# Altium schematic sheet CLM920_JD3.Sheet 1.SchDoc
size 431 x 279 mm
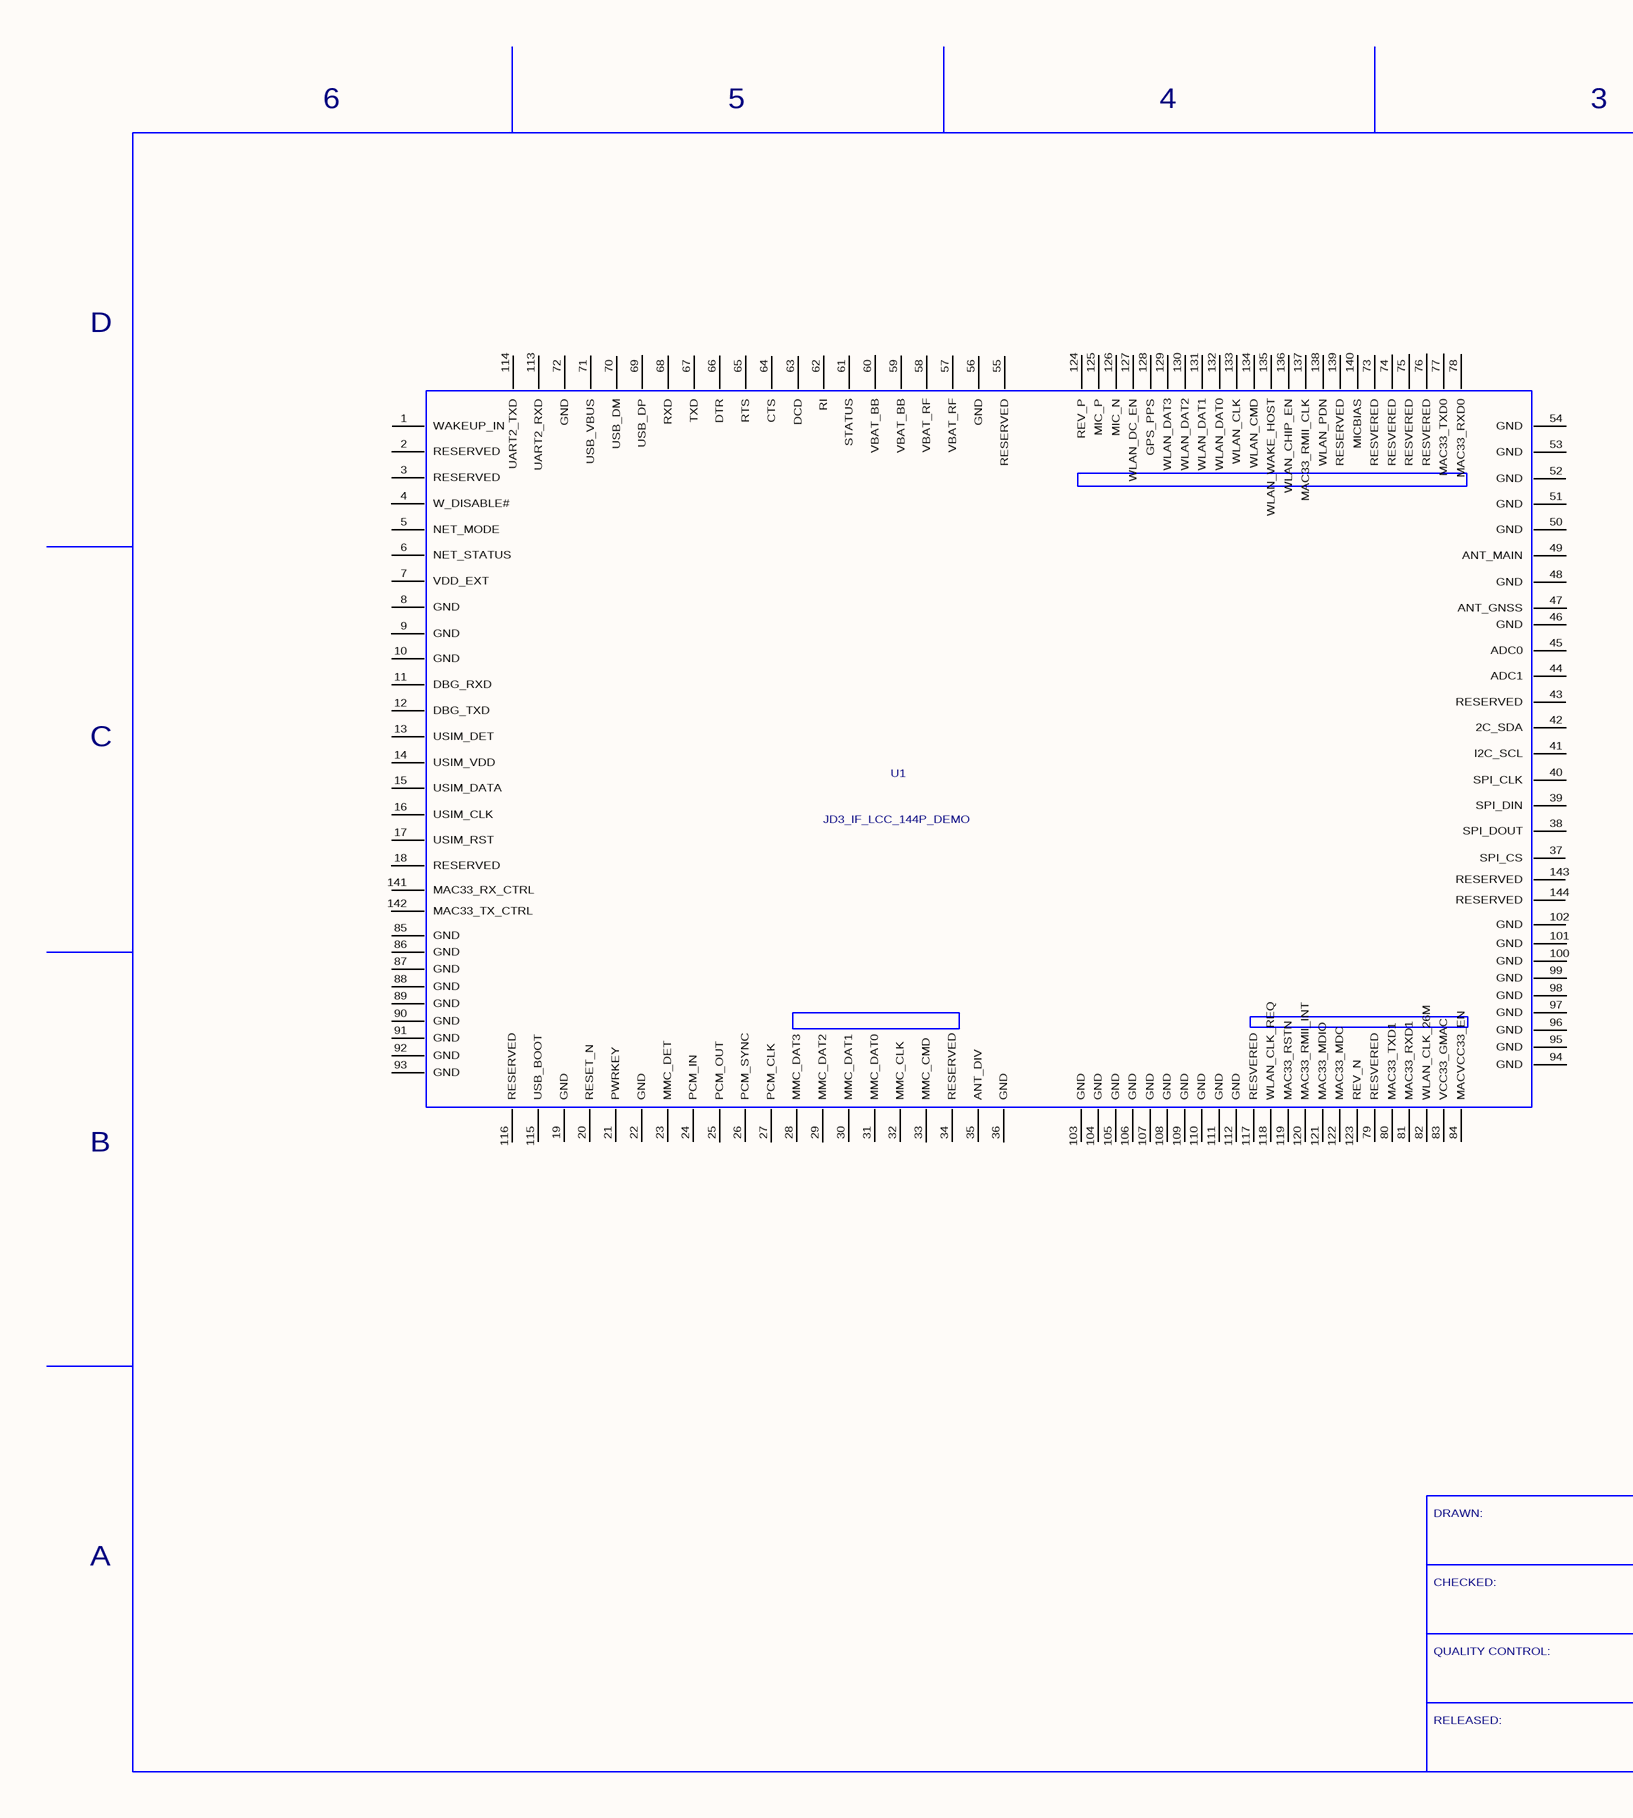
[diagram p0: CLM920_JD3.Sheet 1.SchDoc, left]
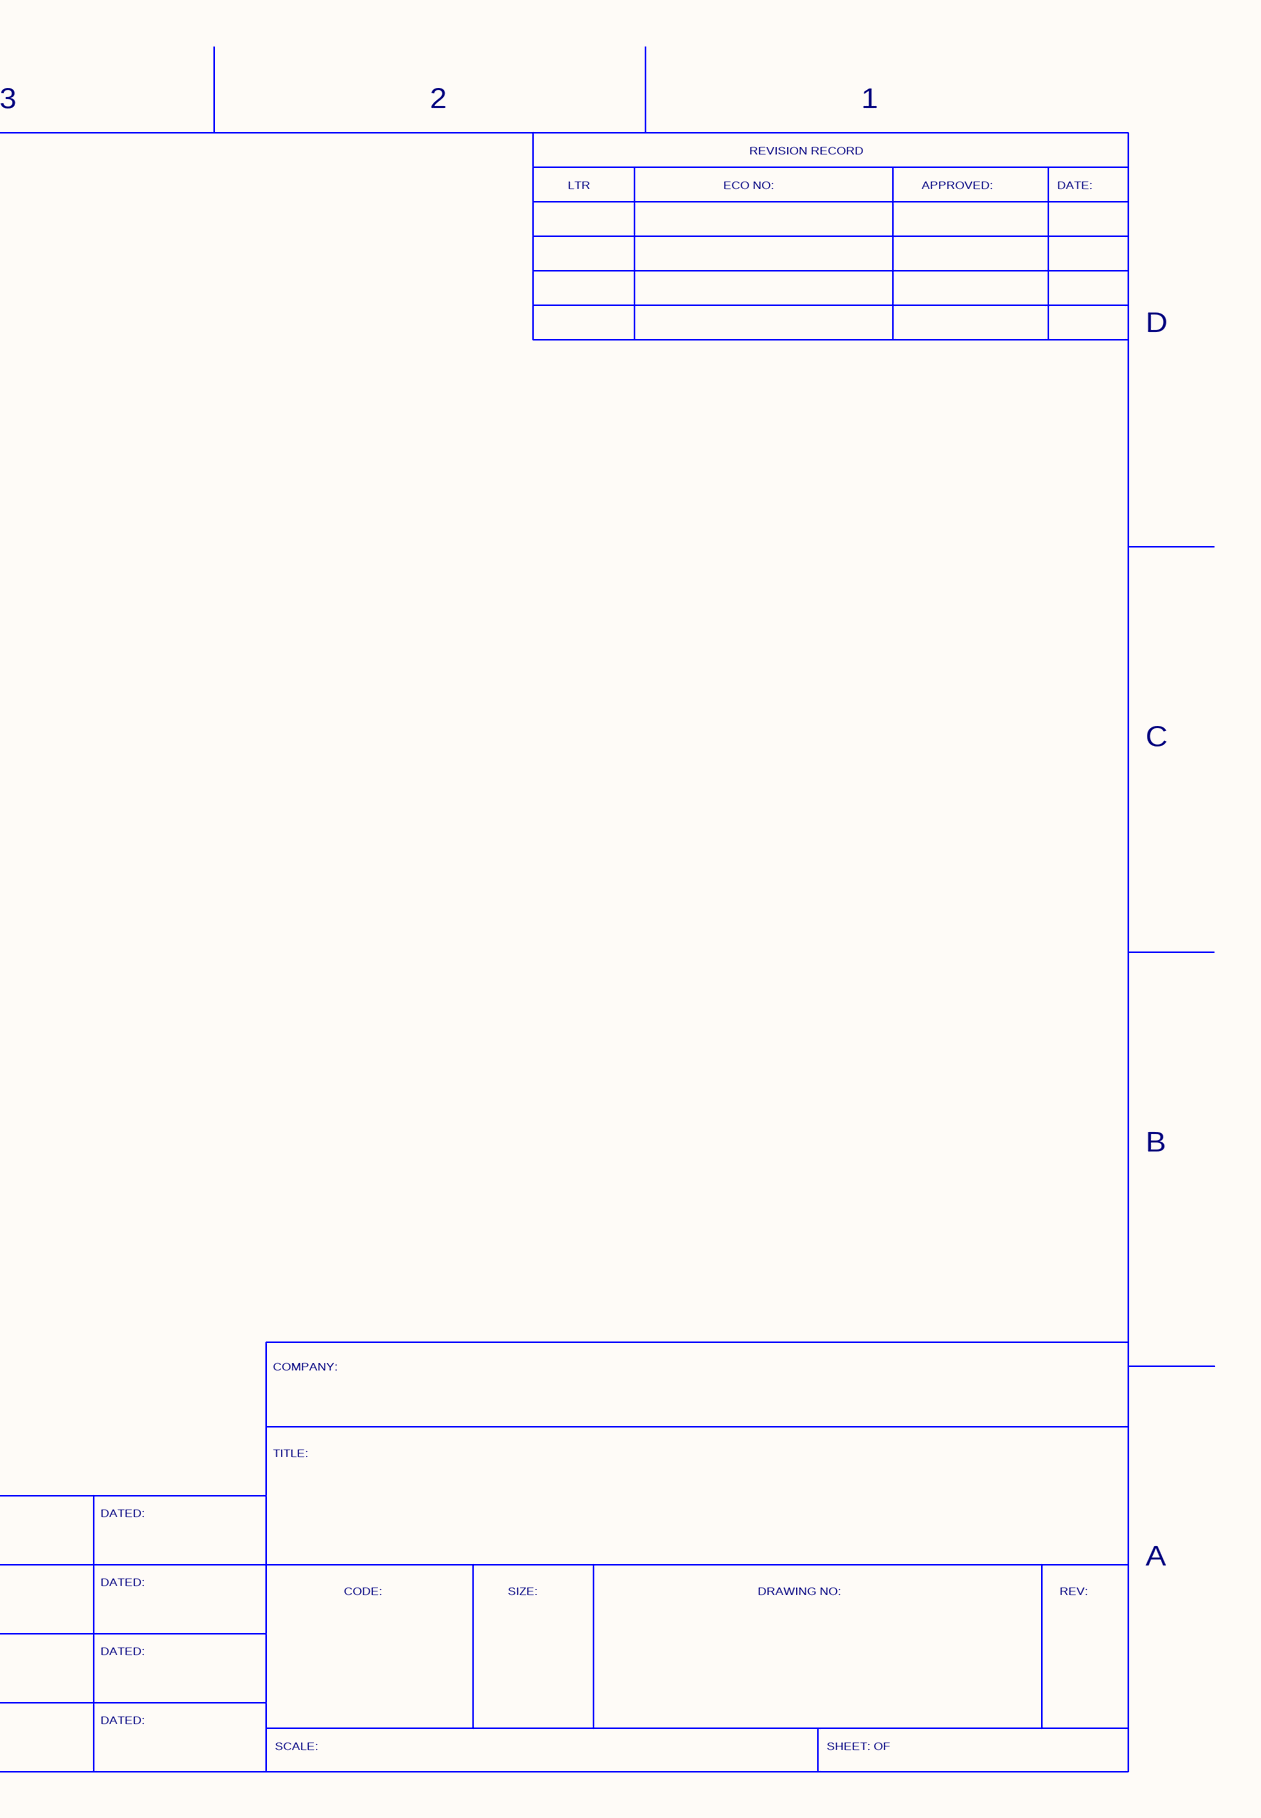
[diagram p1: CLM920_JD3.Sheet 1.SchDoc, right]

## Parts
U1  JD3_IF_LCC_144P_DEMO  [IF_LCC_144P_DEMO]

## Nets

Not connected (* = marked no-connect by the designer): U1 1(WAKEUP_IN) 2(RESERVED) 3(RESERVED) 4(W_DISABLE#) 5(NET_MODE) 6(NET_STATUS) 7(VDD_EXT) 8(GND) 9(GND) 10(GND) 11(DBG_RXD) 12(DBG_TXD) 13(USIM_DET) 14(USIM_VDD) 15(USIM_DATA) 16(USIM_CLK) 17(USIM_RST) 18(RESERVED) 19(GND) 20(RESET_N) 21(PWRKEY) 22(GND) 23(MMC_DET) 24(PCM_IN) 25(PCM_OUT) 26(PCM_SYNC) 27(PCM_CLK) 28(MMC_DAT3) 29(MMC_DAT2) 30(MMC_DAT1) 31(MMC_DAT0) 32(MMC_CLK) 33(MMC_CMD) 34(RESERVED) 35(ANT_DIV) 36(GND) 37(SPI_CS) 38(SPI_DOUT) 39(SPI_DIN) 40(SPI_CLK) 41(I2C_SCL) 42(2C_SDA) 43(RESERVED) 44(ADC1) 45(ADC0) 46(GND) 47(ANT_GNSS) 48(GND) 49(ANT_MAIN) 50(GND) 51(GND) 52(GND) 53(GND) 54(GND) 55(RESERVED) 56(GND) 57(VBAT_RF) 58(VBAT_RF) 59(VBAT_BB) 60(VBAT_BB) 61(STATUS) 62(RI) 63(DCD) 64(CTS) 65(RTS) 66(DTR) 67(TXD) 68(RXD) 69(USB_DP) 70(USB_DM) 71(USB_VBUS) 72(GND) 73(RESVERED) 74(RESVERED) 75(RESVERED) 76(RESVERED) 77(MAC33_TXD0) 78(MAC33_RXD0) 79(RESVERED) 80(MAC33_TXD1) 81(MAC33_RXD1) 82(WLAN_CLK_26M) 83(VCC33_GMAC) 84(MACVCC33_EN) 85(GND) 86(GND) 87(GND) 88(GND) 89(GND) 90(GND) 91(GND) 92(GND) 93(GND) 94(GND) 95(GND) 96(GND) 97(GND) 98(GND) 99(GND) 100(GND) 101(GND) 102(GND) 103(GND) 104(GND) 105(GND) 106(GND) 107(GND) 108(GND) 109(GND) 110(GND) 111(GND) 112(GND) 113(UART2_RXD) 114(UART2_TXD) 115(USB_BOOT) 116(RESERVED) 117(RESVERED) 118(WLAN_CLK_REQ) 119(MAC33_RSTN) 120(MAC33_RMII_INT) 121(MAC33_MDIO) 122(MAC33_MDC) 123(REV_N) 124(REV_P) 125(MIC_P) 126(MIC_N) 127(WLAN_DC_EN) 128(GPS_PPS) 129(WLAN_DAT3) 130(WLAN_DAT2) 131(WLAN_DAT1) 132(WLAN_DAT0) 133(WLAN_CLK) 134(WLAN_CMD) 135(WLAN_WAKE_HOST) 136(WLAN_CHIP_EN) 137(MAC33_RMII_CLK) 138(WLAN_PDN) 139(RESERVED) 140(MICBIAS) 141(MAC33_RX_CTRL) 142(MAC33_TX_CTRL) 143(RESERVED) 144(RESERVED)

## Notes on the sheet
- 6
- 5
- 4
- 3
- 2
- REVISION RECORD
- 1
- LTR
- ECO NO:
- APPROVED:
- DATE:
- D
- C
- B
- COMPANY:
- TITLE:
- DRAWN:
- DATED:
- A
- CHECKED:
- CODE:
- SIZE:
- DRAWING NO:
- REV:
- QUALITY CONTROL:
- RELEASED:
- SCALE:
- SHEET: OF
